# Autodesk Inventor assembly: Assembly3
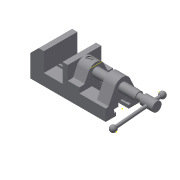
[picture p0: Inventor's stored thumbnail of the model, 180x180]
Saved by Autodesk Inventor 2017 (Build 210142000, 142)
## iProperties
Created: 2016-05
Part Number: Assembly3
Document SubType Name: Assembly
Designer: Sandeep
Author: Sandeep
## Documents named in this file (11)
- C:\Users\Sandeep\Desktop\New folder\joint tut\Assembly3.iam
- C:\Users\Sandeep\Desktop\New folder\joint tut\Base1.ipt
- C:\Users\Sandeep\Desktop\New folder\joint tut\base plate.ipt
- C:\Users\Sandeep\Desktop\New folder\joint tut\vice jaw.ipt
- C:\Users\Sandeep\Desktop\New folder\joint tut\jaw screw.ipt
- C:\Users\Sandeep\Desktop\New folder\joint tut\clamping plate.ipt
- C:\Users\Sandeep\Desktop\New folder\joint tut\Screw Bar.ipt
- C:\Users\Sandeep\Desktop\New folder\joint tut\bar globes.ipt
- C:\Users\Sandeep\Desktop\New folder\joint tut\set scew 1.ipt
- C:\Users\Sandeep\Desktop\New folder\joint tut\set scew 2.ipt
- C:\Users\Sandeep\Desktop\New folder\joint tut\Oval Filister.ipt
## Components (16 placed, 10 different names)
1. Base1:1 — Slider:1, Cylindrical:1, Insert:10, Mate:15, Mate:16, Mate:17, Mate:18, Mate:19, Mate:21, Mate:23
2. base plate:1 — Insert:10, Mate:15, Mate:20, Mate:22
3. base plate:2 — Mate:16, Mate:17, Mate:18, Mate:24, Mate:25, Mate:26
4. vice jaw:1 — Slider:1, Mate:1, Insert:9, Mate:2, Mate:12, Mate:13, Mate:14
5. jaw screw:1 — Cylindrical:1, Mate:1, Cylindrical:2
6. clamping plate:1 — Insert:9, Mate:2, Mate:27, Mate:28, Mate:29, Mate:30
7. Screw Bar:1 — Cylindrical:2, Rigid:2, Rigid:3
8. bar globes:1 — Rigid:2
9. bar globes:2 — Rigid:3
10. Oval Filister:1 — Mate:12, Mate:13, Mate:14
11. set scew 1:1 — Mate:19, Mate:20
12. set scew 1:2 — Mate:21, Mate:22
13. set scew 1:3 — Mate:23, Mate:24
14. set scew 1:4 — Mate:25, Mate:26
15. set scew 2:1 — Mate:27, Mate:28
16. set scew 2:2 — Mate:29, Mate:30
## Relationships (28: Mate 21, CylindricalJoint 2, WeldJoint 2, Insert 2, TranslationJoint 1)
- Slider:1 [TranslationJoint]: Base1:1 ↔ vice jaw:1
- Cylindrical:1: Base1:1 ↔ jaw screw:1
- Mate:1: vice jaw:1 ↔ jaw screw:1
- Cylindrical:2: jaw screw:1 ↔ Screw Bar:1
- Rigid:2 [WeldJoint]: Screw Bar:1 ↔ bar globes:1
- Rigid:3 [WeldJoint]: Screw Bar:1 ↔ bar globes:2
- Insert:9: vice jaw:1 ↔ clamping plate:1
- Mate:2: vice jaw:1 ↔ clamping plate:1
- Mate:12: vice jaw:1 ↔ Oval Filister:1
- Mate:13: vice jaw:1 ↔ Oval Filister:1
- Mate:14: vice jaw:1 ↔ Oval Filister:1
- Insert:10: Base1:1 ↔ base plate:1
- Mate:15: Base1:1 ↔ base plate:1
- Mate:16: Base1:1 ↔ base plate:2
- Mate:17: Base1:1 ↔ base plate:2
- Mate:18: Base1:1 ↔ base plate:2
- Mate:19: Base1:1 ↔ set scew 1:1
- Mate:20: base plate:1 ↔ set scew 1:1
- Mate:21: Base1:1 ↔ set scew 1:2
- Mate:22: base plate:1 ↔ set scew 1:2
- Mate:23: Base1:1 ↔ set scew 1:3
- Mate:24: base plate:2 ↔ set scew 1:3
- Mate:25: base plate:2 ↔ set scew 1:4
- Mate:26: base plate:2 ↔ set scew 1:4
- Mate:27: clamping plate:1 ↔ set scew 2:1
- Mate:28: clamping plate:1 ↔ set scew 2:1
- Mate:29: clamping plate:1 ↔ set scew 2:2
- Mate:30: clamping plate:1 ↔ set scew 2:2
